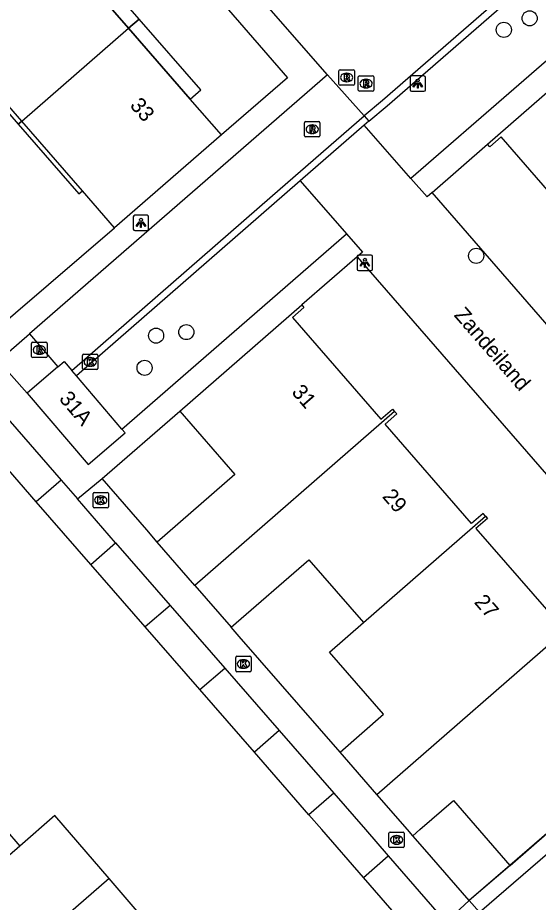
# Model space of a CAD drawing. Extents: x 155888 to 156864, y 383882 to 384671.
# Drawn here: x 156382.6 to 156416.5, y 384245.3 to 384302.8 of the extents above; entities that cross this region are included whole.
import ezdxf

# ---------------------------------------------------------------- set-up
doc = ezdxf.new("R2010")
doc.units = 0
for name, color, linetype in [('IMGEO_Boom', 7, 'Continuous'), ('IMGEO_Groenvoorziening', 7, 'Continuous'), ('IMGEO_Haag', 7, 'Continuous'), ('IMGEO_Kolk', 7, 'Continuous'), ('IMGEO_Lichtpunt', 7, 'Continuous'), ('IMGEO_Muur', 7, 'Continuous'), ('IMGEO_Openbare_ruimte_label', 7, 'Continuous'), ('IMGEO_Pand', 7, 'Continuous'), ('IMGEO_Pand_nummerreeks', 7, 'Continuous'), ('IMGEO_Pand_overbouw', 7, 'Continuous'), ('IMGEO_Rijbaan_lokaal_gesloten', 7, 'Continuous'), ('IMGEO_Rijbaan_lokaal_open', 7, 'Continuous'), ('IMGEO_Rioolput', 7, 'Continuous'), ('IMGEO_Voetpad_open', 7, 'Continuous')]:
    doc.layers.add(name, color=color, linetype=linetype)

msp = doc.modelspace()

# ---------------------------------------------------------------- linework, layer by layer
at = {"layer": 'IMGEO_Boom'}
for centre in [(156415.897, 384302.748), (156414.221, 384301.999), (156412.422, 384287.304), (156391.626, 384282.116), (156393.588, 384282.345), (156390.877, 384280.024)]:
    msp.add_circle(centre, 0.489, dxfattribs=at)
at = {"layer": 'IMGEO_Groenvoorziening'}
msp.add_lwpolyline([(156414.625, 384247.662), (156411.974, 384245.385)], dxfattribs=at)
at = {"layer": 'IMGEO_Haag'}
for points in [[(156412.629, 384244.63), (156417.675, 384248.986), (156430.86, 384260.45)], [(156417.022, 384249.743), (156414.619, 384247.669)], [(156414.619, 384247.669), (156411.974, 384245.385)]]:
    msp.add_lwpolyline(points, dxfattribs=at)
at = {"layer": 'IMGEO_Kolk'}
for p, q in [((156386.841, 384279.981), (156386.841, 384280.833)), ((156386.916, 384280.907), (156387.768, 384280.907)), ((156387.329, 384280.687), (156387.354, 384280.687)), ((156387.842, 384280.833), (156387.842, 384279.981)), ((156387.352, 384280.127), (156387.327, 384280.127)), ((156387.768, 384279.907), (156386.916, 384279.907)), ((156387.527, 384270.994), (156387.527, 384271.846)), ((156387.602, 384271.92), (156388.454, 384271.92)), ((156388.015, 384271.7), (156388.04, 384271.7)), ((156388.528, 384271.846), (156388.528, 384270.994)), ((156388.454, 384270.92), (156387.602, 384270.92)), ((156388.038, 384271.14), (156388.013, 384271.14)), ((156396.799, 384260.342), (156396.799, 384261.194)), ((156396.874, 384261.268), (156397.726, 384261.268)), ((156397.287, 384261.048), (156397.312, 384261.048)), ((156397.8, 384261.194), (156397.8, 384260.342)), ((156397.31, 384260.488), (156397.285, 384260.488)), ((156397.726, 384260.268), (156396.874, 384260.268)), ((156406.753, 384248.908), (156406.753, 384249.76)), ((156406.828, 384249.834), (156407.68, 384249.834)), ((156407.241, 384249.614), (156407.266, 384249.614)), ((156407.754, 384249.76), (156407.754, 384248.908)), ((156407.264, 384249.054), (156407.239, 384249.054)), ((156407.68, 384248.834), (156406.828, 384248.834))]:
    msp.add_line(p, q, dxfattribs=at)
for points in [[(156386.841, 384279.981), (156386.841, 384280.833)], [(156386.916, 384280.907), (156387.768, 384280.907)], [(156387.162, 384280.607), (156387.285, 384280.607), (156387.285, 384280.456), (156387.415, 384280.607), (156387.579, 384280.607), (156387.433, 384280.456), (156387.586, 384280.207), (156387.434, 384280.207), (156387.349, 384280.371), (156387.285, 384280.304), (156387.285, 384280.207), (156387.162, 384280.207), (156387.162, 384280.607)], [(156387.842, 384280.833), (156387.842, 384279.981)], [(156387.768, 384279.907), (156386.916, 384279.907)], [(156387.527, 384270.994), (156387.527, 384271.846)], [(156387.602, 384271.92), (156388.454, 384271.92)], [(156387.848, 384271.62), (156387.971, 384271.62), (156387.971, 384271.469), (156388.101, 384271.62), (156388.265, 384271.62), (156388.119, 384271.469), (156388.272, 384271.22), (156388.12, 384271.22), (156388.035, 384271.384), (156387.971, 384271.317), (156387.971, 384271.22), (156387.848, 384271.22), (156387.848, 384271.62)], [(156388.528, 384271.846), (156388.528, 384270.994)], [(156388.454, 384270.92), (156387.602, 384270.92)], [(156396.799, 384260.342), (156396.799, 384261.194)], [(156396.874, 384261.268), (156397.726, 384261.268)], [(156397.8, 384261.194), (156397.8, 384260.342)], [(156397.12, 384260.968), (156397.243, 384260.968), (156397.243, 384260.817), (156397.373, 384260.968), (156397.537, 384260.968), (156397.391, 384260.817), (156397.544, 384260.568), (156397.392, 384260.568), (156397.307, 384260.732), (156397.243, 384260.665), (156397.243, 384260.568), (156397.12, 384260.568), (156397.12, 384260.968)], [(156397.726, 384260.268), (156396.874, 384260.268)], [(156406.753, 384248.908), (156406.753, 384249.76)], [(156406.828, 384249.834), (156407.68, 384249.834)], [(156407.074, 384249.534), (156407.197, 384249.534), (156407.197, 384249.383), (156407.327, 384249.534), (156407.491, 384249.534), (156407.345, 384249.383), (156407.498, 384249.134), (156407.346, 384249.134), (156407.261, 384249.298), (156407.197, 384249.231), (156407.197, 384249.134), (156407.074, 384249.134), (156407.074, 384249.534)], [(156407.754, 384249.76), (156407.754, 384248.908)], [(156407.68, 384248.834), (156406.828, 384248.834)]]:
    msp.add_lwpolyline(points, dxfattribs=at)
for centre, start, end in [((156386.918, 384280.831), 91.55205, 178.44795), ((156386.918, 384280.831), 91.55205, 178.44795), ((156387.766, 384280.831), 1.55205, 88.44795), ((156387.766, 384280.831), 1.55205, 88.44795), ((156386.918, 384279.983), 181.55205, 268.44795), ((156386.918, 384279.983), 181.55205, 268.44795), ((156387.766, 384279.983), 271.55205, 358.44795), ((156387.766, 384279.983), 271.55205, 358.44795), ((156387.604, 384271.844), 91.55205, 178.44795), ((156387.604, 384271.844), 91.55205, 178.44795), ((156388.452, 384271.844), 1.55205, 88.44795), ((156388.452, 384271.844), 1.55205, 88.44795), ((156387.604, 384270.996), 181.55205, 268.44795), ((156387.604, 384270.996), 181.55205, 268.44795), ((156388.452, 384270.996), 271.55205, 358.44795), ((156388.452, 384270.996), 271.55205, 358.44795), ((156396.876, 384261.192), 91.55205, 178.44795), ((156396.876, 384261.192), 91.55205, 178.44795), ((156397.724, 384261.192), 1.55205, 88.44795), ((156397.724, 384261.192), 1.55205, 88.44795), ((156396.876, 384260.344), 181.55205, 268.44795), ((156396.876, 384260.344), 181.55205, 268.44795), ((156397.724, 384260.344), 271.55205, 358.44795), ((156397.724, 384260.344), 271.55205, 358.44795), ((156406.83, 384249.758), 91.55205, 178.44795), ((156406.83, 384249.758), 91.55205, 178.44795), ((156407.678, 384249.758), 1.55205, 88.44795), ((156407.678, 384249.758), 1.55205, 88.44795), ((156406.83, 384248.91), 181.55205, 268.44795), ((156406.83, 384248.91), 181.55205, 268.44795), ((156407.678, 384248.91), 271.55205, 358.44795), ((156407.678, 384248.91), 271.55205, 358.44795)]:
    msp.add_arc(centre, 0.0765, start, end, dxfattribs=at)
for centre, major_axis, ratio, start_param, end_param in [((156387.328, 384280.407), (-0.387, 0.002), 0.722429, 4.712389, 7.853982), ((156387.353, 384280.407), (-0.39, 0.002), 0.717154, 1.570796, 4.712389), ((156388.014, 384271.42), (-0.387, 0.002), 0.722429, 4.712389, 7.853982), ((156388.039, 384271.42), (-0.39, 0.002), 0.717154, 1.570796, 4.712389), ((156397.286, 384260.768), (-0.387, 0.002), 0.722429, 4.712389, 7.853982), ((156397.311, 384260.768), (-0.39, 0.002), 0.717154, 1.570796, 4.712389), ((156407.24, 384249.334), (-0.387, 0.002), 0.722429, 4.712389, 7.853982), ((156407.265, 384249.334), (-0.39, 0.002), 0.717154, 1.570796, 4.712389)]:
    msp.add_ellipse(centre, major_axis=major_axis, ratio=ratio, start_param=start_param, end_param=end_param, dxfattribs=at)
at = {"layer": 'IMGEO_Lichtpunt'}
for p, q in [((156409.031, 384298.999), (156408.223, 384298.999)), ((156409.031, 384298.999), (156408.223, 384298.999)), ((156408.129, 384298.904), (156408.129, 384298.097)), ((156408.129, 384298.904), (156408.129, 384298.097)), ((156409.125, 384298.097), (156409.125, 384298.904)), ((156409.125, 384298.097), (156409.125, 384298.904)), ((156408.223, 384298.003), (156409.031, 384298.003)), ((156408.223, 384298.003), (156409.031, 384298.003)), ((156390.14, 384289.848), (156390.14, 384289.041)), ((156390.14, 384289.848), (156390.14, 384289.041)), ((156391.042, 384289.943), (156390.234, 384289.943)), ((156391.042, 384289.943), (156390.234, 384289.943)), ((156391.136, 384289.041), (156391.136, 384289.848)), ((156391.136, 384289.041), (156391.136, 384289.848)), ((156390.234, 384288.947), (156391.042, 384288.947)), ((156390.234, 384288.947), (156391.042, 384288.947)), ((156404.691, 384287.251), (156404.691, 384286.444)), ((156404.691, 384287.251), (156404.691, 384286.444)), ((156405.593, 384287.346), (156404.785, 384287.346)), ((156405.593, 384287.346), (156404.785, 384287.346)), ((156405.687, 384286.444), (156405.687, 384287.251)), ((156405.687, 384286.444), (156405.687, 384287.251)), ((156404.785, 384286.35), (156405.593, 384286.35)), ((156404.785, 384286.35), (156405.593, 384286.35))]:
    msp.add_line(p, q, dxfattribs=at)
for points in [[(156408.503, 384298.568), (156408.542, 384298.54), (156408.354, 384298.278), (156408.316, 384298.305), (156408.503, 384298.568)], [(156408.605, 384298.52), (156408.652, 384298.52), (156408.652, 384298.198), (156408.605, 384298.198), (156408.605, 384298.52)], [(156408.715, 384298.54), (156408.753, 384298.567), (156408.94, 384298.305), (156408.901, 384298.277), (156408.715, 384298.54)], [(156390.514, 384289.512), (156390.553, 384289.484), (156390.365, 384289.222), (156390.327, 384289.249), (156390.514, 384289.512)], [(156390.616, 384289.464), (156390.663, 384289.464), (156390.663, 384289.142), (156390.616, 384289.142), (156390.616, 384289.464)], [(156390.726, 384289.484), (156390.764, 384289.511), (156390.951, 384289.249), (156390.912, 384289.221), (156390.726, 384289.484)], [(156405.065, 384286.915), (156405.104, 384286.887), (156404.916, 384286.625), (156404.878, 384286.652), (156405.065, 384286.915)], [(156405.277, 384286.887), (156405.315, 384286.914), (156405.502, 384286.652), (156405.463, 384286.624), (156405.277, 384286.887)], [(156405.167, 384286.867), (156405.214, 384286.867), (156405.214, 384286.545), (156405.167, 384286.545), (156405.167, 384286.867)]]:
    msp.add_lwpolyline(points, dxfattribs=at)
for centre in [(156408.628, 384298.702), (156390.639, 384289.646), (156405.19, 384287.049)]:
    msp.add_circle(centre, 0.0994, dxfattribs=at)
for centre, start, end in [((156408.223, 384298.904), 90, 180), ((156408.223, 384298.904), 90, 180), ((156409.031, 384298.904), 0, 90), ((156409.031, 384298.904), 0, 90), ((156408.223, 384298.097), 180, 270), ((156408.223, 384298.097), 180, 270), ((156409.031, 384298.097), 270, 0), ((156409.031, 384298.097), 270, 360), ((156390.234, 384289.848), 90, 180), ((156390.234, 384289.848), 90, 180), ((156391.042, 384289.848), 0, 90), ((156391.042, 384289.848), 0, 90), ((156390.234, 384289.041), 180, 270), ((156390.234, 384289.041), 180, 270), ((156391.042, 384289.041), 270, 0), ((156391.042, 384289.041), 270, 360), ((156404.785, 384287.251), 90, 180), ((156404.785, 384287.251), 90, 180), ((156405.593, 384287.251), 0, 90), ((156405.593, 384287.251), 0, 90), ((156404.785, 384286.444), 180, 270), ((156404.785, 384286.444), 180, 270), ((156405.593, 384286.444), 270, 0), ((156405.593, 384286.444), 270, 360)]:
    msp.add_arc(centre, 0.0946, start, end, dxfattribs=at)
at = {"layer": 'IMGEO_Muur'}
msp.add_lwpolyline([(156388.119, 384272.839), (156393.156, 384277.208)], dxfattribs=at)
at = {"layer": 'IMGEO_Pand'}
for points in [[(156389.835, 384302.105), (156385.822, 384306.727), (156383.933, 384308.902)], [(156382.893, 384296.069), (156378.943, 384300.617), (156376.983, 384302.874)], [(156382.893, 384296.069), (156389.835, 384302.105)], [(156395.866, 384295.161), (156393.835, 384297.5), (156389.835, 384302.105)], [(156413.155, 384294.555), (156421.071, 384301.467)], [(156388.92, 384289.129), (156386.832, 384291.534), (156382.893, 384296.069)], [(156395.866, 384295.161), (156388.92, 384289.129)], [(156419.169, 384287.633), (156419.037, 384287.785), (156419.792, 384288.441), (156414.054, 384295.046), (156413.3, 384294.388), (156413.155, 384294.555)], [(156393.156, 384277.208), (156401.095, 384284.112)], [(156401.095, 384284.112), (156401.232, 384283.954), (156400.481, 384283.301), (156406.231, 384276.684), (156406.986, 384277.34), (156407.123, 384277.182)], [(156385.245, 384280.084), (156383.252, 384278.385)], [(156385.245, 384280.084), (156385.655, 384280.433), (156386.144, 384279.859)], [(156386.443, 384279.509), (156386.144, 384279.859)], [(156389.407, 384276.029), (156386.443, 384279.509)], [(156383.252, 384278.385), (156387.202, 384273.749), (156389.605, 384275.797), (156389.407, 384276.029)], [(156393.156, 384277.208), (156396.735, 384273.089), (156391.685, 384268.696)], [(156407.123, 384277.182), (156394.142, 384265.872)], [(156413.028, 384270.385), (156412.88, 384270.556), (156412.125, 384269.9), (156406.507, 384276.366), (156407.262, 384277.022), (156407.123, 384277.182)], [(156381.702, 384277.034), (156385.451, 384272.725)], [(156383.836, 384271.321), (156380.088, 384275.63)], [(156385.451, 384272.725), (156383.836, 384271.321)], [(156385.451, 384272.725), (156386.513, 384271.504)], [(156388.995, 384268.651), (156386.52, 384271.496), (156386.513, 384271.504)], [(156387.381, 384267.247), (156383.836, 384271.321)], [(156405.093, 384263.471), (156413.028, 384270.385)], [(156413.028, 384270.385), (156413.156, 384270.238), (156412.402, 384269.583), (156418.022, 384263.115), (156418.777, 384263.771), (156418.935, 384263.589)], [(156387.381, 384267.247), (156388.995, 384268.651)], [(156388.995, 384268.651), (156392.536, 384264.581)], [(156394.142, 384265.872), (156391.685, 384268.696)], [(156396.494, 384263.169), (156401.551, 384267.546), (156405.093, 384263.471)], [(156390.921, 384263.178), (156387.381, 384267.247)], [(156394.142, 384265.872), (156396.494, 384263.169)], [(156392.536, 384264.581), (156390.921, 384263.178)], [(156392.536, 384264.581), (156396.083, 384260.505)], [(156403.577, 384255.034), (156406.41, 384257.503), (156402.886, 384261.548), (156405.093, 384263.471)], [(156405.962, 384252.288), (156418.935, 384263.589)], [(156394.468, 384259.101), (156390.921, 384263.178)], [(156394.468, 384259.101), (156396.083, 384260.505)], [(156396.083, 384260.505), (156399.624, 384256.435)], [(156398.009, 384255.031), (156394.468, 384259.101)], [(156399.624, 384256.435), (156398.009, 384255.031)], [(156399.624, 384256.435), (156403.168, 384252.361)], [(156401.553, 384250.957), (156398.009, 384255.031)], [(156405.962, 384252.288), (156403.577, 384255.034)], [(156379.222, 384253.005), (156381.834, 384250), (156382.765, 384248.929)], [(156403.168, 384252.361), (156401.553, 384250.957)], [(156403.168, 384252.361), (156405.222, 384250), (156406.709, 384248.29)], [(156408.298, 384249.599), (156407.95, 384250), (156405.962, 384252.288)], [(156408.298, 384249.599), (156408.759, 384250), (156410.944, 384251.901), (156414.619, 384247.669)], [(156388.568, 384246.825), (156385.046, 384250.912), (156382.765, 384248.929)], [(156405.094, 384246.887), (156402.386, 384250), (156401.553, 384250.957)], [(156414.625, 384247.662), (156417.022, 384249.743)], [(156382.765, 384248.929), (156374.882, 384242.077)], [(156405.094, 384246.887), (156406.709, 384248.29)], [(156406.709, 384248.29), (156410.449, 384243.991)], [(156414.619, 384247.669), (156414.625, 384247.662)], [(156388.568, 384246.825), (156378.422, 384238.006)], [(156392.093, 384242.735), (156388.568, 384246.825)], [(156408.835, 384242.587), (156405.094, 384246.887)]]:
    msp.add_lwpolyline(points, dxfattribs=at)
at = {"layer": 'IMGEO_Pand_overbouw'}
for points in [[(156385.822, 384306.727), (156389.835, 384302.105), (156390.52, 384302.701), (156386.498, 384307.328)], [(156393.835, 384297.5), (156394.528, 384298.091), (156390.52, 384302.701), (156389.835, 384302.105)], [(156382.893, 384296.069), (156378.943, 384300.617), (156378.717, 384300.42), (156382.667, 384295.872)], [(156386.832, 384291.534), (156382.893, 384296.069), (156382.667, 384295.872), (156386.606, 384291.337)]]:
    msp.add_lwpolyline(points, close=True, dxfattribs=at)
at = {"layer": 'IMGEO_Rijbaan_lokaal_gesloten'}
for points in [[(156466.597, 384349.82), (156461.728, 384345.598), (156460.345, 384344.417), (156453.722, 384338.62), (156444.208, 384330.292), (156436.91, 384323.995), (156406.345, 384297.398), (156405.149, 384296.413)], [(156402.759, 384299.068), (156398.191, 384304.319)], [(156405.149, 384296.413), (156402.759, 384299.068)]]:
    msp.add_lwpolyline(points, dxfattribs=at)
at = {"layer": 'IMGEO_Rijbaan_lokaal_open'}
for points in [[(156405.446, 384296.062), (156406.642, 384297.047), (156437.211, 384323.647), (156438.632, 384324.873)], [(156402.759, 384299.068), (156383.39, 384282.224)], [(156386.144, 384279.859), (156399.192, 384291.22), (156405.149, 384296.413)], [(156405.149, 384296.413), (156405.446, 384296.062)], [(156405.14, 384295.795), (156400.994, 384292.18)], [(156405.446, 384296.062), (156405.14, 384295.795)], [(156408.176, 384292.336), (156405.14, 384295.795)], [(156400.994, 384292.18), (156386.443, 384279.509)], [(156400.994, 384292.18), (156404.001, 384288.734)], [(156409.564, 384291.419), (156409.233, 384291.131), (156408.176, 384292.336)], [(156432.92, 384263.843), (156433.259, 384264.139), (156409.564, 384291.419)], [(156404.001, 384288.734), (156405.041, 384287.543), (156404.697, 384287.244)], [(156404.697, 384287.244), (156428.436, 384259.936), (156428.797, 384260.259)], [(156383.39, 384282.224), (156385.245, 384280.084)]]:
    msp.add_lwpolyline(points, dxfattribs=at)
at = {"layer": 'IMGEO_Rioolput'}
for p, q in [((156403.507, 384298.473), (156403.507, 384299.325)), ((156403.582, 384299.399), (156404.434, 384299.399)), ((156403.995, 384299.179), (156404.02, 384299.179)), ((156404.508, 384299.325), (156404.508, 384298.473)), ((156404.84, 384299.006), (156405.692, 384299.006)), ((156404.018, 384298.619), (156403.993, 384298.619)), ((156404.765, 384298.08), (156404.765, 384298.932)), ((156405.253, 384298.786), (156405.278, 384298.786)), ((156405.766, 384298.932), (156405.766, 384298.08)), ((156404.434, 384298.399), (156403.582, 384298.399)), ((156405.692, 384298.006), (156404.84, 384298.006)), ((156405.276, 384298.226), (156405.251, 384298.226)), ((156401.267, 384295.11), (156401.267, 384295.962)), ((156401.342, 384296.036), (156402.194, 384296.036)), ((156401.755, 384295.816), (156401.78, 384295.816)), ((156402.268, 384295.962), (156402.268, 384295.11)), ((156402.194, 384295.036), (156401.342, 384295.036)), ((156401.778, 384295.256), (156401.753, 384295.256)), ((156383.537, 384280.76), (156383.537, 384281.612)), ((156383.612, 384281.686), (156384.464, 384281.686)), ((156384.025, 384281.466), (156384.05, 384281.466)), ((156384.538, 384281.612), (156384.538, 384280.76)), ((156384.464, 384280.686), (156383.612, 384280.686)), ((156384.048, 384280.906), (156384.023, 384280.906))]:
    msp.add_line(p, q, dxfattribs=at)
for points in [[(156403.507, 384298.473), (156403.507, 384299.325)], [(156403.582, 384299.399), (156404.434, 384299.399)], [(156404.096, 384299.097), (156403.844, 384299.099), (156403.844, 384298.699)], [(156404.022, 384299.018), (156403.968, 384299.018), (156403.968, 384298.937)], [(156404.508, 384299.325), (156404.508, 384298.473)], [(156404.84, 384299.006), (156405.692, 384299.006)], [(156403.844, 384298.699), (156403.968, 384298.699), (156403.968, 384298.861), (156403.979, 384298.861)], [(156403.968, 384298.937), (156404.02, 384298.937)], [(156404.026, 384298.832), (156404.097, 384298.699), (156404.237, 384298.699), (156404.172, 384298.825)], [(156404.765, 384298.08), (156404.765, 384298.932)], [(156405.354, 384298.704), (156405.102, 384298.706), (156405.102, 384298.306)], [(156405.102, 384298.306), (156405.226, 384298.306), (156405.226, 384298.468), (156405.237, 384298.468)], [(156405.28, 384298.625), (156405.226, 384298.625), (156405.226, 384298.544)], [(156405.226, 384298.544), (156405.278, 384298.544)], [(156405.284, 384298.439), (156405.355, 384298.306), (156405.495, 384298.306), (156405.43, 384298.432)], [(156405.766, 384298.932), (156405.766, 384298.08)], [(156404.434, 384298.399), (156403.582, 384298.399)], [(156405.692, 384298.006), (156404.84, 384298.006)], [(156401.267, 384295.11), (156401.267, 384295.962)], [(156401.342, 384296.036), (156402.194, 384296.036)], [(156401.856, 384295.734), (156401.604, 384295.736), (156401.604, 384295.336)], [(156401.782, 384295.655), (156401.728, 384295.655), (156401.728, 384295.574)], [(156401.728, 384295.574), (156401.78, 384295.574)], [(156402.268, 384295.962), (156402.268, 384295.11)], [(156402.194, 384295.036), (156401.342, 384295.036)], [(156401.604, 384295.336), (156401.728, 384295.336), (156401.728, 384295.498), (156401.739, 384295.498)], [(156401.786, 384295.469), (156401.857, 384295.336), (156401.997, 384295.336), (156401.932, 384295.462)], [(156383.537, 384280.76), (156383.537, 384281.612)], [(156383.612, 384281.686), (156384.464, 384281.686)], [(156384.126, 384281.384), (156383.874, 384281.386), (156383.874, 384280.986)], [(156384.052, 384281.305), (156383.998, 384281.305), (156383.998, 384281.224)], [(156383.998, 384281.224), (156384.05, 384281.224)], [(156384.538, 384281.612), (156384.538, 384280.76)], [(156384.464, 384280.686), (156383.612, 384280.686)], [(156383.874, 384280.986), (156383.998, 384280.986), (156383.998, 384281.148), (156384.009, 384281.148)], [(156384.056, 384281.119), (156384.127, 384280.986), (156384.267, 384280.986), (156384.202, 384281.112)]]:
    msp.add_lwpolyline(points, dxfattribs=at)
for centre, radius, start, end in [((156403.584, 384299.323), 0.0765, 91.55205, 178.44795), ((156403.584, 384299.323), 0.0765, 91.55205, 178.44795), ((156404.028, 384298.922), 0.0964, 77.00612, 93.18647), ((156404.042, 384298.979), 0.0378, 276.66336, 79.67722), ((156404.095, 384298.987), 0.109, 350.36119, 89.41601), ((156404.432, 384299.323), 0.0765, 1.55205, 88.44795), ((156404.432, 384299.323), 0.0765, 1.55205, 88.44795), ((156404.842, 384298.93), 0.0765, 91.55205, 178.44795), ((156404.842, 384298.93), 0.0765, 91.55205, 178.44795), ((156405.69, 384298.93), 0.0765, 1.55205, 88.44795), ((156405.69, 384298.93), 0.0765, 1.55205, 88.44795), ((156403.584, 384298.475), 0.0765, 181.55205, 268.44795), ((156403.584, 384298.475), 0.0765, 181.55205, 268.44795), ((156403.978, 384298.808), 0.0533, 26.02933, 88.69889), ((156404.004, 384299.126), 0.19, 274.7715, 282.96867), ((156404.093, 384298.987), 0.112, 277.58423, 350.98172), ((156404.077, 384298.772), 0.108, 29.51342, 73.79051), ((156404.432, 384298.475), 0.0765, 271.55205, 358.44795), ((156404.432, 384298.475), 0.0765, 271.55205, 358.44795), ((156405.236, 384298.415), 0.0533, 26.02933, 88.69889), ((156405.262, 384298.733), 0.19, 274.7715, 282.96867), ((156405.286, 384298.529), 0.0964, 77.00612, 93.18647), ((156405.3, 384298.586), 0.0378, 276.66336, 79.67722), ((156405.353, 384298.594), 0.109, 350.36119, 89.41601), ((156405.351, 384298.594), 0.112, 277.58423, 350.98172), ((156405.335, 384298.379), 0.108, 29.51342, 73.79051), ((156404.842, 384298.082), 0.0765, 181.55205, 268.44795), ((156404.842, 384298.082), 0.0765, 181.55205, 268.44795), ((156405.69, 384298.082), 0.0765, 271.55205, 358.44795), ((156405.69, 384298.082), 0.0765, 271.55205, 358.44795), ((156401.344, 384295.96), 0.0765, 91.55205, 178.44795), ((156401.344, 384295.96), 0.0765, 91.55205, 178.44795), ((156401.764, 384295.763), 0.19, 274.7715, 282.96867), ((156401.788, 384295.559), 0.0964, 77.00612, 93.18647), ((156401.802, 384295.616), 0.0378, 276.66336, 79.67722), ((156401.855, 384295.624), 0.109, 350.36119, 89.41601), ((156401.853, 384295.624), 0.112, 277.58423, 350.98172), ((156402.192, 384295.96), 0.0765, 1.55205, 88.44795), ((156402.192, 384295.96), 0.0765, 1.55205, 88.44795), ((156401.344, 384295.112), 0.0765, 181.55205, 268.44795), ((156401.344, 384295.112), 0.0765, 181.55205, 268.44795), ((156401.738, 384295.445), 0.0533, 26.02933, 88.69889), ((156401.837, 384295.409), 0.108, 29.51342, 73.79051), ((156402.192, 384295.112), 0.0765, 271.55205, 358.44795), ((156402.192, 384295.112), 0.0765, 271.55205, 358.44795), ((156383.614, 384281.61), 0.0765, 91.55205, 178.44795), ((156383.614, 384281.61), 0.0765, 91.55205, 178.44795), ((156384.034, 384281.413), 0.19, 274.7715, 282.96867), ((156384.058, 384281.209), 0.0964, 77.00612, 93.18647), ((156384.072, 384281.266), 0.0378, 276.66336, 79.67722), ((156384.125, 384281.274), 0.109, 350.36119, 89.41601), ((156384.123, 384281.274), 0.112, 277.58423, 350.98172), ((156384.107, 384281.059), 0.108, 29.51342, 73.79051), ((156384.462, 384281.61), 0.0765, 1.55205, 88.44795), ((156384.462, 384281.61), 0.0765, 1.55205, 88.44795), ((156383.614, 384280.762), 0.0765, 181.55205, 268.44795), ((156383.614, 384280.762), 0.0765, 181.55205, 268.44795), ((156384.008, 384281.095), 0.0533, 26.02933, 88.69889), ((156384.462, 384280.762), 0.0765, 271.55205, 358.44795), ((156384.462, 384280.762), 0.0765, 271.55205, 358.44795)]:
    msp.add_arc(centre, radius, start, end, dxfattribs=at)
for centre, major_axis, ratio, start_param, end_param in [((156403.994, 384298.899), (-0.387, 0.002), 0.722429, 4.712389, 7.853982), ((156404.019, 384298.899), (-0.39, 0.002), 0.717154, 1.570796, 4.712389), ((156405.252, 384298.506), (-0.387, 0.002), 0.722429, 4.712389, 7.853982), ((156405.277, 384298.506), (-0.39, 0.002), 0.717154, 1.570796, 4.712389), ((156401.754, 384295.536), (-0.387, 0.002), 0.722429, 4.712389, 7.853982), ((156401.779, 384295.536), (-0.39, 0.002), 0.717154, 1.570796, 4.712389), ((156384.024, 384281.186), (-0.387, 0.002), 0.722429, 4.712389, 7.853982), ((156384.049, 384281.186), (-0.39, 0.002), 0.717154, 1.570796, 4.712389)]:
    msp.add_ellipse(centre, major_axis=major_axis, ratio=ratio, start_param=start_param, end_param=end_param, dxfattribs=at)
at = {"layer": 'IMGEO_Voetpad_open'}
for points in [[(156364.376, 384340.144), (156400.159, 384298.882), (156395.866, 384295.161)], [(156441.648, 384321.401), (156408.176, 384292.336)], [(156409.564, 384291.419), (156413.155, 384294.555)], [(156380.323, 384281.751), (156388.92, 384289.129)], [(156389.407, 384276.029), (156404.001, 384288.734)], [(156404.697, 384287.244), (156401.095, 384284.112)], [(156383.252, 384278.385), (156381.369, 384280.482), (156383.39, 384282.224)], [(156388.119, 384272.839), (156393.156, 384277.208)], [(156386.513, 384271.504), (156388.119, 384272.839)], [(156391.685, 384268.696), (156391.014, 384269.481), (156388.119, 384272.839)], [(156403.577, 384255.034), (156397.021, 384262.56), (156396.494, 384263.169)], [(156411.974, 384245.385), (156409.078, 384248.712), (156408.298, 384249.599)], [(156410.449, 384243.991), (156411.974, 384245.385)], [(156411.974, 384245.385), (156412.629, 384244.63)]]:
    msp.add_lwpolyline(points, dxfattribs=at)

# ---------------------------------------------------------------- texts
at = {"layer": 'IMGEO_Openbare_ruimte_label'}
msp.add_text('Zandeiland', height=1, rotation=310.98653, dxfattribs=at).set_placement((156410.937, 384283.428))
at = {"layer": 'IMGEO_Pand_nummerreeks'}
for s, rotation, p in [('33', 310.97232, (156389.876, 384297.057)), ('31', 310.98902, (156400.384, 384278.413)), ('31A', 310.42868, (156385.271, 384277.988)), ('29', 310.98902, (156406.277, 384271.632)), ('27', 310.98919, (156412.243, 384264.766))]:
    msp.add_text(s, height=1, rotation=rotation, dxfattribs=at).set_placement(p)

doc.saveas('drawing.dxf')
